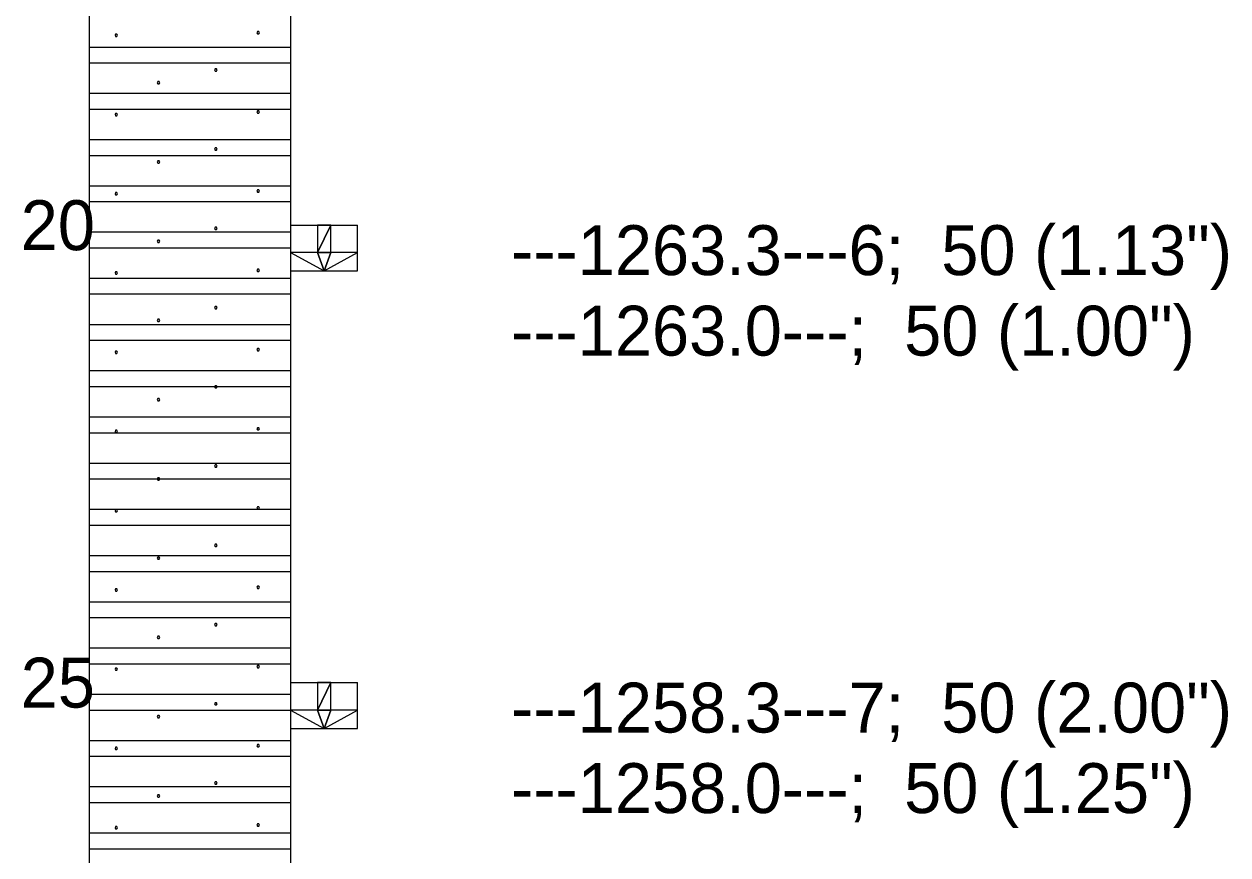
# Model space of a CAD drawing. Extents: x 2150161.5 to 2150203.1, y 143779.5 to 143868.5.
# Drawn here: x 2150191.798 to 2150194.79, y 143823.25 to 143825.314 of the extents above; entities that cross this region are included whole.
import ezdxf

# ---------------------------------------------------------------- set-up
doc = ezdxf.new("R2010")
doc.units = 0
doc.layers.add('Default', color=7, linetype='Continuous')

msp = doc.modelspace()

# ---------------------------------------------------------------- linework, layer by layer
at = {"layer": 'Default'}
for points in [[(2150191.9604, 143829.3595), (2150191.9604, 143817.2004)], [(2150192.4604, 143829.3595), (2150192.4604, 143817.2004)], [(2150192.3836, 143825.2924), (2150192.3819, 143825.2953), (2150192.3787, 143825.2953), (2150192.377, 143825.2924), (2150192.3787, 143825.2896), (2150192.3819, 143825.2896), (2150192.3836, 143825.2924)], [(2150192.0308, 143825.2859), (2150192.0292, 143825.2888), (2150192.0259, 143825.2888), (2150192.0243, 143825.2859), (2150192.0259, 143825.2831), (2150192.0292, 143825.2831), (2150192.0308, 143825.2859)], [(2150191.9604, 143825.2567), (2150192.4604, 143825.2567)], [(2150191.9604, 143825.2173), (2150192.4604, 143825.2173)], [(2150192.2781, 143825.1999), (2150192.2764, 143825.2027), (2150192.2731, 143825.2027), (2150192.2715, 143825.1999), (2150192.2731, 143825.1971), (2150192.2764, 143825.1971), (2150192.2781, 143825.1999)], [(2150192.1355, 143825.168), (2150192.1338, 143825.1709), (2150192.1306, 143825.1709), (2150192.1289, 143825.1681), (2150192.1306, 143825.1652), (2150192.1338, 143825.1652), (2150192.1355, 143825.168)], [(2150191.9604, 143825.1418), (2150192.4604, 143825.1418)], [(2150191.9604, 143825.1025), (2150192.4604, 143825.1025)], [(2150192.0308, 143825.0891), (2150192.0292, 143825.0919), (2150192.0259, 143825.0919), (2150192.0243, 143825.0891), (2150192.0259, 143825.0862), (2150192.0292, 143825.0862), (2150192.0308, 143825.0891)], [(2150192.3836, 143825.0956), (2150192.3819, 143825.0985), (2150192.3787, 143825.0985), (2150192.377, 143825.0956), (2150192.3787, 143825.0928), (2150192.3819, 143825.0928), (2150192.3836, 143825.0956)], [(2150191.9604, 143825.027), (2150192.4604, 143825.027)], [(2150192.2781, 143825.0031), (2150192.2764, 143825.0059), (2150192.2731, 143825.0059), (2150192.2715, 143825.0031), (2150192.2731, 143825.0002), (2150192.2764, 143825.0002), (2150192.2781, 143825.0031)], [(2150191.9604, 143824.9876), (2150192.4604, 143824.9876)], [(2150192.1355, 143824.9712), (2150192.1338, 143824.9741), (2150192.1306, 143824.9741), (2150192.1289, 143824.9712), (2150192.1306, 143824.9684), (2150192.1338, 143824.9684), (2150192.1355, 143824.9712)], [(2150191.9604, 143824.9122), (2150192.4604, 143824.9122)], [(2150192.0308, 143824.8922), (2150192.0292, 143824.8951), (2150192.0259, 143824.8951), (2150192.0243, 143824.8922), (2150192.0259, 143824.8894), (2150192.0292, 143824.8894), (2150192.0308, 143824.8922)], [(2150192.3836, 143824.8987), (2150192.3819, 143824.9016), (2150192.3787, 143824.9016), (2150192.377, 143824.8987), (2150192.3787, 143824.8959), (2150192.3819, 143824.8959), (2150192.3836, 143824.8987)], [(2150191.9604, 143824.8728), (2150192.4604, 143824.8728)], [(2150191.9604, 143824.7974), (2150192.4604, 143824.7974)], [(2150192.2781, 143824.8062), (2150192.2764, 143824.809), (2150192.2731, 143824.809), (2150192.2715, 143824.8062), (2150192.2731, 143824.8034), (2150192.2764, 143824.8034), (2150192.2781, 143824.8062)], [(2150192.4604, 143824.8141), (2150192.6271, 143824.8141)], [(2150192.6271, 143824.7004), (2150192.6271, 143824.8141)], [(2150191.9604, 143824.758), (2150192.4604, 143824.758)], [(2150192.1355, 143824.7743), (2150192.1338, 143824.7772), (2150192.1306, 143824.7772), (2150192.1289, 143824.7744), (2150192.1306, 143824.7715), (2150192.1338, 143824.7715), (2150192.1355, 143824.7743)], [(2150192.0308, 143824.6954), (2150192.0292, 143824.6982), (2150192.0259, 143824.6982), (2150192.0243, 143824.6954), (2150192.0259, 143824.6925), (2150192.0292, 143824.6925), (2150192.0308, 143824.6954)], [(2150192.3836, 143824.7019), (2150192.3819, 143824.7048), (2150192.3787, 143824.7048), (2150192.377, 143824.7019), (2150192.3787, 143824.6991), (2150192.3819, 143824.6991), (2150192.3836, 143824.7019)], [(2150192.4604, 143824.7004), (2150192.6271, 143824.7004)], [(2150191.9604, 143824.6825), (2150192.4604, 143824.6825)], [(2150191.9604, 143824.6432), (2150192.4604, 143824.6432)], [(2150192.2781, 143824.6094), (2150192.2764, 143824.6122), (2150192.2731, 143824.6122), (2150192.2715, 143824.6094), (2150192.2731, 143824.6065), (2150192.2764, 143824.6065), (2150192.2781, 143824.6094)], [(2150192.1355, 143824.5775), (2150192.1338, 143824.5804), (2150192.1306, 143824.5804), (2150192.1289, 143824.5775), (2150192.1306, 143824.5747), (2150192.1338, 143824.5747), (2150192.1355, 143824.5775)], [(2150191.9604, 143824.5677), (2150192.4604, 143824.5677)], [(2150191.9604, 143824.5283), (2150192.4604, 143824.5283)], [(2150192.0308, 143824.4985), (2150192.0292, 143824.5014), (2150192.0259, 143824.5014), (2150192.0243, 143824.4985), (2150192.0259, 143824.4957), (2150192.0292, 143824.4957), (2150192.0308, 143824.4985)], [(2150192.3836, 143824.505), (2150192.3819, 143824.5079), (2150192.3787, 143824.5079), (2150192.377, 143824.505), (2150192.3787, 143824.5022), (2150192.3819, 143824.5022), (2150192.3836, 143824.505)], [(2150191.9604, 143824.4529), (2150192.4604, 143824.4529)], [(2150191.9604, 143824.4135), (2150192.4604, 143824.4135)], [(2150192.2781, 143824.4125), (2150192.2764, 143824.4153), (2150192.2731, 143824.4153), (2150192.2715, 143824.4125), (2150192.2731, 143824.4097), (2150192.2764, 143824.4097), (2150192.2781, 143824.4125)], [(2150192.1355, 143824.3806), (2150192.1338, 143824.3835), (2150192.1306, 143824.3835), (2150192.1289, 143824.3807), (2150192.1306, 143824.3778), (2150192.1338, 143824.3778), (2150192.1355, 143824.3806)], [(2150191.9604, 143824.338), (2150192.4604, 143824.338)], [(2150192.3836, 143824.3082), (2150192.3819, 143824.3111), (2150192.3787, 143824.3111), (2150192.377, 143824.3082), (2150192.3787, 143824.3054), (2150192.3819, 143824.3054), (2150192.3836, 143824.3082)], [(2150191.9604, 143824.2987), (2150192.4604, 143824.2987)], [(2150192.0308, 143824.3017), (2150192.0292, 143824.3045), (2150192.0259, 143824.3045), (2150192.0243, 143824.3017), (2150192.0259, 143824.2988), (2150192.0292, 143824.2988), (2150192.0308, 143824.3017)], [(2150191.9604, 143824.2232), (2150192.4604, 143824.2232)], [(2150192.2781, 143824.2157), (2150192.2764, 143824.2185), (2150192.2731, 143824.2185), (2150192.2715, 143824.2157), (2150192.2731, 143824.2128), (2150192.2764, 143824.2128), (2150192.2781, 143824.2157)], [(2150191.9604, 143824.1838), (2150192.4604, 143824.1838)], [(2150192.1355, 143824.1838), (2150192.1338, 143824.1867), (2150192.1306, 143824.1867), (2150192.1289, 143824.1838), (2150192.1306, 143824.181), (2150192.1338, 143824.181), (2150192.1355, 143824.1838)], [(2150191.9604, 143824.1084), (2150192.4604, 143824.1084)], [(2150192.0308, 143824.1048), (2150192.0292, 143824.1077), (2150192.0259, 143824.1077), (2150192.0243, 143824.1048), (2150192.0259, 143824.102), (2150192.0292, 143824.102), (2150192.0308, 143824.1048)], [(2150192.3836, 143824.1113), (2150192.3819, 143824.1142), (2150192.3787, 143824.1142), (2150192.377, 143824.1113), (2150192.3787, 143824.1085), (2150192.3819, 143824.1085), (2150192.3836, 143824.1113)], [(2150191.9604, 143824.069), (2150192.4604, 143824.069)], [(2150192.2781, 143824.0188), (2150192.2764, 143824.0216), (2150192.2731, 143824.0216), (2150192.2715, 143824.0188), (2150192.2731, 143824.016), (2150192.2764, 143824.016), (2150192.2781, 143824.0188)], [(2150191.9604, 143823.9936), (2150192.4604, 143823.9936)], [(2150192.1355, 143823.9869), (2150192.1338, 143823.9898), (2150192.1306, 143823.9898), (2150192.1289, 143823.987), (2150192.1306, 143823.9841), (2150192.1338, 143823.9841), (2150192.1355, 143823.9869)], [(2150191.9604, 143823.9542), (2150192.4604, 143823.9542)], [(2150192.0308, 143823.908), (2150192.0292, 143823.9108), (2150192.0259, 143823.9108), (2150192.0243, 143823.908), (2150192.0259, 143823.9051), (2150192.0292, 143823.9051), (2150192.0308, 143823.908)], [(2150192.3836, 143823.9145), (2150192.3819, 143823.9174), (2150192.3787, 143823.9174), (2150192.377, 143823.9145), (2150192.3787, 143823.9117), (2150192.3819, 143823.9117), (2150192.3836, 143823.9145)], [(2150191.9604, 143823.8787), (2150192.4604, 143823.8787)], [(2150191.9604, 143823.8394), (2150192.4604, 143823.8394)], [(2150192.2781, 143823.822), (2150192.2764, 143823.8248), (2150192.2731, 143823.8248), (2150192.2715, 143823.822), (2150192.2731, 143823.8191), (2150192.2764, 143823.8191), (2150192.2781, 143823.822)], [(2150192.1355, 143823.7901), (2150192.1338, 143823.793), (2150192.1306, 143823.793), (2150192.1289, 143823.7901), (2150192.1306, 143823.7873), (2150192.1338, 143823.7873), (2150192.1355, 143823.7901)], [(2150191.9604, 143823.7639), (2150192.4604, 143823.7639)], [(2150191.9604, 143823.7245), (2150192.4604, 143823.7245)], [(2150192.0308, 143823.7111), (2150192.0292, 143823.714), (2150192.0259, 143823.714), (2150192.0243, 143823.7111), (2150192.0259, 143823.7083), (2150192.0292, 143823.7083), (2150192.0308, 143823.7111)], [(2150192.3836, 143823.7176), (2150192.3819, 143823.7205), (2150192.3787, 143823.7205), (2150192.377, 143823.7176), (2150192.3787, 143823.7148), (2150192.3819, 143823.7148), (2150192.3836, 143823.7176)], [(2150191.9604, 143823.6491), (2150192.4604, 143823.6491)], [(2150192.4604, 143823.6777), (2150192.6271, 143823.6777)], [(2150192.6271, 143823.5641), (2150192.6271, 143823.6777)], [(2150192.2781, 143823.6251), (2150192.2764, 143823.6279), (2150192.2731, 143823.6279), (2150192.2715, 143823.6251), (2150192.2731, 143823.6223), (2150192.2764, 143823.6223), (2150192.2781, 143823.6251)], [(2150191.9604, 143823.6097), (2150192.4604, 143823.6097)], [(2150192.1355, 143823.5932), (2150192.1338, 143823.5961), (2150192.1306, 143823.5961), (2150192.1289, 143823.5933), (2150192.1306, 143823.5904), (2150192.1338, 143823.5904), (2150192.1355, 143823.5932)], [(2150192.4604, 143823.5641), (2150192.6271, 143823.5641)], [(2150191.9604, 143823.5342), (2150192.4604, 143823.5342)], [(2150192.0308, 143823.5143), (2150192.0292, 143823.5171), (2150192.0259, 143823.5171), (2150192.0243, 143823.5143), (2150192.0259, 143823.5114), (2150192.0292, 143823.5114), (2150192.0308, 143823.5143)], [(2150192.3836, 143823.5208), (2150192.3819, 143823.5237), (2150192.3787, 143823.5237), (2150192.377, 143823.5208), (2150192.3787, 143823.518), (2150192.3819, 143823.518), (2150192.3836, 143823.5208)], [(2150191.9604, 143823.4949), (2150192.4604, 143823.4949)], [(2150191.9604, 143823.4194), (2150192.4604, 143823.4194)], [(2150192.2781, 143823.4283), (2150192.2764, 143823.4311), (2150192.2731, 143823.4311), (2150192.2715, 143823.4283), (2150192.2731, 143823.4254), (2150192.2764, 143823.4254), (2150192.2781, 143823.4283)], [(2150191.9604, 143823.38), (2150192.4604, 143823.38)], [(2150192.1355, 143823.3964), (2150192.1338, 143823.3993), (2150192.1306, 143823.3993), (2150192.1289, 143823.3964), (2150192.1306, 143823.3936), (2150192.1338, 143823.3936), (2150192.1355, 143823.3964)], [(2150192.0308, 143823.3174), (2150192.0292, 143823.3203), (2150192.0259, 143823.3203), (2150192.0243, 143823.3174), (2150192.0259, 143823.3146), (2150192.0292, 143823.3146), (2150192.0308, 143823.3174)], [(2150192.3836, 143823.3239), (2150192.3819, 143823.3268), (2150192.3787, 143823.3268), (2150192.377, 143823.3239), (2150192.3787, 143823.3211), (2150192.3819, 143823.3211), (2150192.3836, 143823.3239)], [(2150191.9604, 143823.3046), (2150192.4604, 143823.3046)], [(2150191.9604, 143823.2652), (2150192.4604, 143823.2652)]]:
    msp.add_lwpolyline(points, dxfattribs=at)
for points in [[(2150192.5271, 143824.7459), (2150192.5604, 143824.7459), (2150192.5604, 143824.8141), (2150192.5271, 143824.7459)], [(2150192.5271, 143824.7459), (2150192.5604, 143824.8141), (2150192.5271, 143824.8141), (2150192.5271, 143824.7459)], [(2150192.5271, 143824.7459), (2150192.4604, 143824.7459), (2150192.5437, 143824.7004), (2150192.5271, 143824.7459)], [(2150192.5271, 143824.7459), (2150192.5437, 143824.7004), (2150192.5604, 143824.7459), (2150192.5271, 143824.7459)], [(2150192.5437, 143824.7004), (2150192.6271, 143824.7459), (2150192.5604, 143824.7459), (2150192.5437, 143824.7004)], [(2150192.5271, 143823.6095), (2150192.5604, 143823.6095), (2150192.5604, 143823.6777), (2150192.5271, 143823.6095)], [(2150192.5271, 143823.6095), (2150192.5604, 143823.6777), (2150192.5271, 143823.6777), (2150192.5271, 143823.6095)], [(2150192.5271, 143823.6095), (2150192.4604, 143823.6095), (2150192.5437, 143823.5641), (2150192.5271, 143823.6095)], [(2150192.5271, 143823.6095), (2150192.5437, 143823.5641), (2150192.5604, 143823.6095), (2150192.5271, 143823.6095)], [(2150192.5437, 143823.5641), (2150192.6271, 143823.6095), (2150192.5604, 143823.6095), (2150192.5437, 143823.5641)]]:
    msp.add_lwpolyline(points, close=True, dxfattribs=at)

# ---------------------------------------------------------------- texts
for s, p in [('20', (2150191.79, 143824.7521)), ('---1263.3---6;  50 (1.13")', (2150193.0084, 143824.6901)), ('---1263.0---;  50 (1.00")', (2150193.0084, 143824.4901)), ('25', (2150191.79, 143823.6157)), ('---1258.3---7;  50 (2.00")', (2150193.0084, 143823.5537)), ('---1258.0---;  50 (1.25")', (2150193.0084, 143823.3537))]:
    msp.add_text(s, height=0.124, dxfattribs=at).set_placement(p)

doc.saveas('drawing.dxf')
